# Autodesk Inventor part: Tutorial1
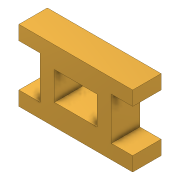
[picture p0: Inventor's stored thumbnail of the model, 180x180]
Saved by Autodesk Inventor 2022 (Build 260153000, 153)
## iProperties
Created: 2021-03
Part Number: Tutorial1
Material: Brass, Soft Yellow
Document SubType Name: Modeling
Designer: ASUS Laptop
Density: 8.47 g/cm^3
Appearance: Brass - Satin
Author: ASUS Laptop
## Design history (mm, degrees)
sketch "Sketch1"
  geometry: L1 (0, 0)-(80, 0); L2 (80, 0)-(80, 10); L3 (80, 10)-(65, 10); L4 (65, 10)-(65, 40); L5 (65, 40)-(80, 40); L6 (80, 40)-(80, 50); L7 (80, 50)-(0, 50); L8 (0, 50)-(0, 40); L9 (0, 40)-(15, 40); L10 (15, 40)-(15, 10); L11 (15, 10)-(0, 10); L12 (0, 0)-(0, 10); L13 (25, 15)-(55, 15); L14 (55, 15)-(55, 35); L15 (55, 35)-(25, 35); L16 (25, 35)-(25, 15)
  constraints: 32 end point, 9 perpendicular, 7 point on line, 3 parallel, 2 horizontal
  dimensions: "d0" = 80 distance between parallel lines of L2 L12; "d1" = 10 distance between parallel lines of L1 L11; "d2" = 10 distance between parallel lines of L9 L7; "d3" = 30 distance between parallel lines of L11 L9; "d4" = 30 distance between parallel lines of L14 L16; "d5" = 10 distance between parallel lines of L10 L16; "d6" = 10 distance between parallel lines of L4 L14; "d7" = 20 distance between parallel lines of L13 L15; "d8" = 15 distance between parallel lines of L13 L1
extrude "Extrusion1" new body sketch "Sketch1" distance "d11" = 20; taper "d12" = 0 deg
body "Solid1"
